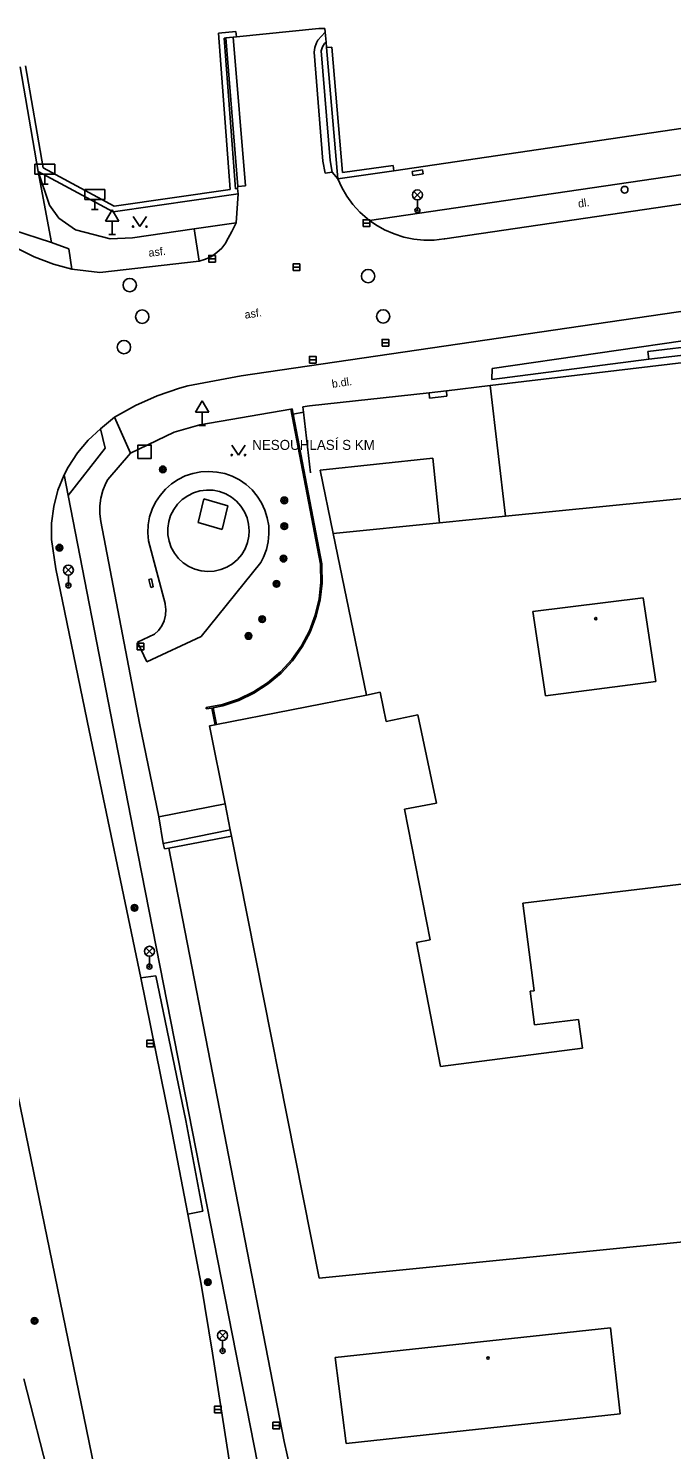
# Model space of a CAD drawing. Extents: x -640201 to -639641, y -1044739 to -1044317.
# Drawn here: x -640117.2 to -640069, y -1044489 to -1044382.5 of the extents above; entities that cross this region are included whole.
import ezdxf

# ---------------------------------------------------------------- set-up
doc = ezdxf.new("R2010")
doc.units = 0
for name, color, linetype in [('Budovy', 7, 'Continuous'), ('Ploty', 7, 'Continuous'), ('Popis objektů', 7, 'Continuous'), ('Popis povrchů', 7, 'Continuous'), ('Pris-HUP', 7, 'Continuous'), ('Rozhraní ploch 1', 7, 'Continuous'), ('Rozhraní ploch 2', 7, 'Continuous'), ('Sloupy_označník', 7, 'Continuous'), ('Vstup na pozemky', 7, 'Continuous'), ('Znaky doprava', 7, 'Continuous'), ('Znaky kanalizace', 7, 'Continuous'), ('Znaky voda', 7, 'Continuous'), ('Značky doprava', 7, 'Continuous'), ('Značky KM', 7, 'Continuous'), ('Značky předmětů', 7, 'Continuous'), ('Šachty ner_', 7, 'Continuous')]:
    doc.layers.add(name, color=color, linetype=linetype)

msp = doc.modelspace()

# ---------------------------------------------------------------- linework, layer by layer
at = {"layer": 'Budovy'}
for p, q in [((-640082.6, -1044409.251), (-640062.223, -1044406.828)), ((-640085.87, -1044409.64), (-640082.6, -1044409.251)), ((-640082.6, -1044409.251), (-640081.44, -1044419.03)), ((-640096.133, -1044410.776), (-640087.17, -1044409.78)), ((-640085.87, -1044409.64), (-640087.17, -1044409.78)), ((-640087.17, -1044409.78), (-640087.127, -1044410.178)), ((-640085.827, -1044410.038), (-640087.127, -1044410.178)), ((-640085.87, -1044409.64), (-640085.827, -1044410.038)), ((-640096.62, -1044410.83), (-640096.133, -1044410.776)), ((-640096.62, -1044410.83), (-640096.574, -1044411.241)), ((-640096.574, -1044411.241), (-640096.068, -1044415.799)), ((-640095.34, -1044415.58), (-640086.88, -1044414.7)), ((-640086.88, -1044414.7), (-640086.4, -1044419.53)), ((-640081.44, -1044419.03), (-640061.28, -1044417.02)), ((-640086.4, -1044419.53), (-640081.44, -1044419.03)), ((-640079.38, -1044426.18), (-640071.11, -1044425.16)), ((-640071.11, -1044425.16), (-640070.18, -1044431.44)), ((-640079.38, -1044426.18), (-640078.44, -1044432.5)), ((-640078.44, -1044432.5), (-640070.18, -1044431.44)), ((-640103.101, -1044434.657), (-640091.86, -1044432.45)), ((-640091.86, -1044432.45), (-640090.84, -1044432.23)), ((-640090.84, -1044432.23), (-640090.38, -1044434.43)), ((-640090.38, -1044434.43), (-640088.01, -1044433.93)), ((-640088.01, -1044433.93), (-640086.62, -1044440.55)), ((-640103.62, -1044434.76), (-640103.199, -1044434.677)), ((-640103.62, -1044434.76), (-640102.459, -1044440.613)), ((-640103.199, -1044434.677), (-640103.101, -1044434.657)), ((-640102.459, -1044440.613), (-640102.073, -1044442.562)), ((-640089, -1044441.01), (-640086.62, -1044440.55)), ((-640089, -1044441.01), (-640087.09, -1044450.79)), ((-640102.073, -1044442.562), (-640101.98, -1044443.03)), ((-640101.98, -1044443.03), (-640095.411, -1044476.154)), ((-640080.14, -1044448.05), (-640061.06, -1044445.76)), ((-640080.14, -1044448.05), (-640079.3, -1044454.62)), ((-640088.12, -1044450.99), (-640087.09, -1044450.79)), ((-640088.12, -1044450.99), (-640086.31, -1044460.29)), ((-640079.6, -1044454.66), (-640079.3, -1044454.62)), ((-640079.6, -1044454.66), (-640079.27, -1044457.18)), ((-640079.27, -1044457.18), (-640075.96, -1044456.76)), ((-640075.96, -1044456.76), (-640075.68, -1044458.93)), ((-640086.31, -1044460.29), (-640075.68, -1044458.93)), ((-640095.411, -1044476.154), (-640065.45, -1044473.17)), ((-640094.2, -1044482.12), (-640073.56, -1044479.89)), ((-640073.56, -1044479.89), (-640072.84, -1044486.33)), ((-640094.2, -1044482.12), (-640093.38, -1044488.55)), ((-640093.38, -1044488.55), (-640072.84, -1044486.33))]:
    msp.add_line(p, q, dxfattribs=at)
at = {"layer": 'Ploty'}
for p, q in [((-640102.958, -1044382.826), (-640101.645, -1044382.712)), ((-640102.958, -1044382.826), (-640102.083, -1044394.544)), ((-640101.61, -1044383.11), (-640101.645, -1044382.712)), ((-640095.44, -1044382.48), (-640094.99, -1044382.47)), ((-640094.99, -1044382.47), (-640094.95, -1044382.76)), ((-640101.686, -1044394.485), (-640102.53, -1044383.19)), ((-640094.85, -1044383.9), (-640094.451, -1044383.866)), ((-640094.85, -1044383.9), (-640094.02, -1044393.74)), ((-640093.657, -1044393.284), (-640094.451, -1044383.866)), ((-640025.49, -1044383.64), (-640089.8, -1044393.14)), ((-640116.46, -1044393.19), (-640117.81, -1044385.35)), ((-640116.099, -1044392.931), (-640117.416, -1044385.282)), ((-640110.86, -1044396.22), (-640116.46, -1044393.19)), ((-640110.786, -1044395.805), (-640116.099, -1044392.931)), ((-640089.8, -1044393.14), (-640094.02, -1044393.74)), ((-640089.856, -1044392.744), (-640093.657, -1044393.284)), ((-640089.8, -1044393.14), (-640089.856, -1044392.744)), ((-640102.083, -1044394.544), (-640110.786, -1044395.805)), ((-640101.686, -1044394.485), (-640101.52, -1044394.46)), ((-640101.47, -1044394.86), (-640101.52, -1044394.46)), ((-640101.47, -1044394.86), (-640110.86, -1044396.22)), ((-640097.52, -1044411.02), (-640097.422, -1044411.001)), ((-640095.31, -1044422.63), (-640097.52, -1044411.02)), ((-640097.348, -1044411.389), (-640097.422, -1044411.001)), ((-640097.348, -1044411.389), (-640096.574, -1044411.241)), ((-640095.211, -1044422.618), (-640097.348, -1044411.389)), ((-640103.877, -1044433.489), (-640103.89, -1044433.39)), ((-640103.199, -1044434.677), (-640103.449, -1044433.424)), ((-640103.101, -1044434.657), (-640103.351, -1044433.406)), ((-640106.67, -1044443.92), (-640101.98, -1044443.03)), ((-640098.02, -1044488.4), (-640106.67, -1044443.92))]:
    msp.add_line(p, q, dxfattribs=at)
for points in [[(-640102.53, -1044383.19), (-640102.406, -1044383.179), (-640101.843, -1044383.13), (-640101.61, -1044383.11)], [(-640096.733, -1044428.751), (-640096.143, -1044427.639), (-640095.7, -1044426.461), (-640095.409, -1044425.237), (-640095.275, -1044423.985), (-640095.301, -1044422.727), (-640095.31, -1044422.63)], [(-640096.671, -1044428.841), (-640096.073, -1044427.727), (-640095.621, -1044426.545), (-640095.321, -1044425.316), (-640095.178, -1044424.059), (-640095.196, -1044422.794), (-640095.211, -1044422.618)], [(-640103.89, -1044433.39), (-640102.655, -1044433.148), (-640101.46, -1044432.75), (-640100.326, -1044432.205), (-640099.27, -1044431.521), (-640098.309, -1044430.708), (-640097.459, -1044429.78), (-640096.733, -1044428.751)], [(-640103.877, -1044433.489), (-640103.449, -1044433.424), (-640103.351, -1044433.406), (-640102.636, -1044433.246), (-640101.435, -1044432.848), (-640100.294, -1044432.302), (-640099.231, -1044431.616), (-640098.262, -1044430.802), (-640097.405, -1044429.872), (-640096.671, -1044428.841)]]:
    msp.add_lwpolyline(points, dxfattribs=at)
at = {"layer": 'Pris-HUP'}
for p, q in [((-640087.656, -1044393.073), (-640088.436, -1044393.193)), ((-640088.436, -1044393.193), (-640088.39, -1044393.49)), ((-640088.39, -1044393.49), (-640087.61, -1044393.37)), ((-640087.656, -1044393.073), (-640087.61, -1044393.37)), ((-640107.98, -1044423.74), (-640108.175, -1044423.786)), ((-640108.035, -1044424.376), (-640108.175, -1044423.786)), ((-640107.84, -1044424.33), (-640108.035, -1044424.376)), ((-640107.84, -1044424.33), (-640107.98, -1044423.74))]:
    msp.add_line(p, q, dxfattribs=at)
at = {"layer": 'Rozhraní ploch 1'}
for p, q in [((-640091.64, -1044396.86), (-640004.24, -1044384.05)), ((-640003.91, -1044386.19), (-640086, -1044398.25)), ((-640094.02, -1044393.74), (-640094.44, -1044393.25)), ((-640101.52, -1044394.46), (-640101.495, -1044394.327)), ((-640101.25, -1044408.51), (-640001.47, -1044393.91)), ((-640082.44, -1044407.96), (-640004.02, -1044396.55)), ((-640113.95, -1044400.53), (-640111.86, -1044400.78)), ((-640111.86, -1044400.78), (-640104.41, -1044399.91)), ((-640070.7, -1044407.27), (-640082.47, -1044408.8)), ((-640082.47, -1044408.8), (-640082.44, -1044407.96)), ((-640105.25, -1044409.26), (-640101.25, -1044408.51)), ((-640111.79, -1044412.49), (-640110.74, -1044411.62)), ((-640104.35, -1044412.18), (-640097.52, -1044411.02)), ((-640111.24, -1044416.3), (-640109.54, -1044414.32)), ((-640101.774, -1044541.352), (-640127.52, -1044416.154)), ((-640114.23, -1044417.48), (-640114.52, -1044415.93)), ((-640110.86, -1044434.83), (-640114.23, -1044417.48)), ((-640108.88, -1044434.55), (-640111.78, -1044419.44)), ((-640115.14, -1044422.98), (-640115.47, -1044420.79)), ((-640108.21, -1044420.89), (-640106.96, -1044425.59)), ((-640112.66, -1044435.11), (-640115.14, -1044422.98)), ((-640104.26, -1044428.06), (-640099.79, -1044422.52)), ((-640107.76, -1044427.89), (-640109.02, -1044428.48)), ((-640109.02, -1044428.48), (-640108.325, -1044429.964)), ((-640104.26, -1044428.06), (-640108.325, -1044429.964)), ((-640108.98, -1044444.45), (-640110.86, -1044434.83)), ((-640107.43, -1044441.57), (-640108.88, -1044434.55)), ((-640108.78, -1044453.65), (-640112.66, -1044435.11)), ((-640102.459, -1044440.613), (-640107.43, -1044441.57)), ((-640107.1, -1044443.58), (-640102.073, -1044442.562)), ((-640107.01, -1044443.98), (-640107.1, -1044443.58)), ((-640096.96, -1044505.67), (-640108.98, -1044444.45)), ((-640106.67, -1044443.92), (-640107.01, -1044443.98)), ((-640107.64, -1044453.49), (-640108.78, -1044453.65)), ((-640106.54, -1044464.61), (-640108.78, -1044453.65)), ((-640105.4, -1044464.34), (-640107.64, -1044453.49)), ((-640105.26, -1044471.36), (-640106.54, -1044464.61)), ((-640104.13, -1044471.13), (-640105.4, -1044464.34)), ((-640105.26, -1044471.36), (-640104.13, -1044471.13)), ((-640104.26, -1044476.62), (-640105.26, -1044471.36)), ((-640103.4, -1044481.78), (-640104.26, -1044476.62)), ((-640099.61, -1044505.95), (-640103.4, -1044481.78)), ((-640117.535, -1044483.704), (-640108.638, -1044518.358))]:
    msp.add_line(p, q, dxfattribs=at)
for points in [[(-640116.46, -1044393.19), (-640115.62, -1044395.73), (-640114.93, -1044396.69), (-640113.67, -1044397.58), (-640111.08, -1044398.25), (-640109.395, -1044398.163)], [(-640094.02, -1044393.74), (-640093.714, -1044394.397), (-640093.327, -1044395.057), (-640092.873, -1044395.673), (-640092.357, -1044396.238), (-640091.785, -1044396.747), (-640091.64, -1044396.86), (-640091.164, -1044397.193), (-640090.499, -1044397.572), (-640089.798, -1044397.879), (-640089.069, -1044398.111), (-640088.319, -1044398.266), (-640087.558, -1044398.343), (-640086.793, -1044398.339), (-640086.032, -1044398.255), (-640086, -1044398.25)], [(-640102.37, -1044398.47), (-640101.95, -1044397.7), (-640101.62, -1044397.05), (-640101.47, -1044394.86)], [(-640109.395, -1044398.163), (-640104.78, -1044397.49), (-640101.62, -1044397.05)], [(-640104.41, -1044399.91), (-640103.932, -1044399.772), (-640103.482, -1044399.56), (-640103.072, -1044399.278), (-640102.712, -1044398.934), (-640102.412, -1044398.537), (-640102.37, -1044398.47)], [(-640118.16, -1044398.9), (-640116.775, -1044399.601), (-640115.325, -1044400.155), (-640113.95, -1044400.53)], [(-640110.74, -1044411.62), (-640109.186, -1044410.747), (-640107.561, -1044410.016), (-640105.876, -1044409.434), (-640105.25, -1044409.26)], [(-640111.79, -1044412.49), (-640112.719, -1044413.338), (-640113.533, -1044414.297), (-640114.219, -1044415.351), (-640114.52, -1044415.93)], [(-640109.54, -1044414.32), (-640106.28, -1044412.73), (-640104.35, -1044412.18)], [(-640108.21, -1044420.89), (-640108.258, -1044420.289), (-640108.227, -1044419.687), (-640108.116, -1044419.095), (-640107.927, -1044418.523), (-640107.665, -1044417.98), (-640107.333, -1044417.477), (-640106.938, -1044417.022), (-640106.485, -1044416.624), (-640105.984, -1044416.289), (-640105.443, -1044416.023), (-640104.872, -1044415.831), (-640104.281, -1044415.717), (-640103.679, -1044415.681), (-640103.078, -1044415.726), (-640102.488, -1044415.849), (-640101.92, -1044416.05)], [(-640114.52, -1044415.93), (-640114.989, -1044417.097), (-640115.307, -1044418.313), (-640115.467, -1044419.56), (-640115.47, -1044420.79)], [(-640111.78, -1044419.44), (-640111.861, -1044418.856), (-640111.861, -1044418.267), (-640111.782, -1044417.683), (-640111.625, -1044417.115), (-640111.393, -1044416.573), (-640111.24, -1044416.3)], [(-640101.92, -1044416.05), (-640101.383, -1044416.324), (-640100.887, -1044416.667), (-640100.441, -1044417.072), (-640100.053, -1044417.533), (-640099.729, -1044418.041), (-640099.474, -1044418.587), (-640099.295, -1044419.163), (-640099.193, -1044419.757), (-640099.171, -1044420.359), (-640099.228, -1044420.959), (-640099.364, -1044421.546), (-640099.577, -1044422.11), (-640099.79, -1044422.52)], [(-640100.653, -1044420.132), (-640100.693, -1044419.64), (-640100.812, -1044419.161), (-640101.006, -1044418.707), (-640101.271, -1044418.29), (-640101.6, -1044417.921), (-640101.984, -1044417.611), (-640102.413, -1044417.366), (-640102.876, -1044417.193), (-640103.36, -1044417.098), (-640103.854, -1044417.081), (-640104.344, -1044417.145), (-640104.817, -1044417.287), (-640105.261, -1044417.503), (-640105.665, -1044417.787), (-640106.017, -1044418.134), (-640106.309, -1044418.532), (-640106.54, -1044418.99), (-640106.683, -1044419.443), (-640106.755, -1044419.931), (-640106.748, -1044420.425)], [(-640106.748, -1044420.425), (-640106.661, -1044420.911), (-640106.496, -1044421.377), (-640106.259, -1044421.811), (-640105.955, -1044422.2), (-640105.593, -1044422.535), (-640105.181, -1044422.808), (-640104.73, -1044423.01), (-640104.253, -1044423.138), (-640103.762, -1044423.186), (-640103.269, -1044423.155), (-640102.787, -1044423.045), (-640102.33, -1044422.858), (-640101.908, -1044422.601), (-640101.534, -1044422.279), (-640101.217, -1044421.9), (-640100.964, -1044421.476), (-640100.783, -1044421.016), (-640100.679, -1044420.533), (-640100.653, -1044420.132)], [(-640107.76, -1044427.89), (-640107.452, -1044427.601), (-640107.204, -1044427.259), (-640107.03, -1044426.89), (-640106.921, -1044426.468), (-640106.896, -1044426.046), (-640106.951, -1044425.628), (-640106.96, -1044425.59)]]:
    msp.add_lwpolyline(points, dxfattribs=at)
at = {"layer": 'Rozhraní ploch 2'}
for p, q in [((-640094.95, -1044382.76), (-640095.5, -1044383.36)), ((-640101.495, -1044394.327), (-640102.406, -1044383.179)), ((-640100.92, -1044394.28), (-640101.843, -1044383.13)), ((-640095.79, -1044384.26), (-640095.14, -1044392.41)), ((-640095.25, -1044384.14), (-640094.58, -1044392.36)), ((-640095.14, -1044392.41), (-640094.97, -1044393.31)), ((-640094.58, -1044392.36), (-640094.44, -1044393.25)), ((-640115.48, -1044398.51), (-640116.46, -1044393.19)), ((-640094.97, -1044393.31), (-640094.44, -1044393.25)), ((-640101.495, -1044394.327), (-640100.92, -1044394.28)), ((-640115.48, -1044398.51), (-640118.39, -1044397.57)), ((-640104.41, -1044399.91), (-640104.78, -1044397.49)), ((-640114.17, -1044398.99), (-640115.48, -1044398.51)), ((-640113.95, -1044400.53), (-640114.17, -1044398.99)), ((-640008.92, -1044399.39), (-640070.77, -1044406.69)), ((-640006.727, -1044399.735), (-640070.7, -1044407.27)), ((-640070.77, -1044406.69), (-640070.7, -1044407.27)), ((-640110.74, -1044411.62), (-640109.54, -1044414.32)), ((-640111.46, -1044413.93), (-640111.79, -1044412.49)), ((-640114.23, -1044417.48), (-640111.46, -1044413.93)), ((-640095.34, -1044415.58), (-640094.36, -1044420.33)), ((-640104.48, -1044419.52), (-640104.05, -1044417.73)), ((-640104.05, -1044417.73), (-640102.25, -1044418.25)), ((-640102.68, -1044420.04), (-640102.25, -1044418.25)), ((-640102.68, -1044420.04), (-640104.48, -1044419.52)), ((-640094.36, -1044420.33), (-640086.4, -1044419.53)), ((-640094.36, -1044420.33), (-640091.86, -1044432.45)), ((-640107.1, -1044443.58), (-640107.43, -1044441.57))]:
    msp.add_line(p, q, dxfattribs=at)
for points in [[(-640095.79, -1044384.26), (-640095.741, -1044383.897), (-640095.614, -1044383.554), (-640095.5, -1044383.36)], [(-640095.25, -1044384.14), (-640095.162, -1044383.859), (-640095, -1044383.61), (-640094.885, -1044383.496)]]:
    msp.add_lwpolyline(points, dxfattribs=at)
at = {"layer": 'Sloupy_označník'}
for centre, radius in [((-640107.12, -1044415.53), 0.25), ((-640107.12, -1044415.53), 0.158), ((-640107.12, -1044415.53), 0.05), ((-640098.02, -1044417.85), 0.25), ((-640098.02, -1044417.85), 0.158), ((-640098.02, -1044417.85), 0.05), ((-640098.02, -1044419.79), 0.25), ((-640098.02, -1044419.79), 0.158), ((-640098.02, -1044419.79), 0.05), ((-640114.88, -1044421.4), 0.25), ((-640114.88, -1044421.4), 0.158), ((-640114.88, -1044421.4), 0.05), ((-640098.08, -1044422.22), 0.25), ((-640098.08, -1044422.22), 0.158), ((-640098.08, -1044422.22), 0.05), ((-640098.6, -1044424.11), 0.25), ((-640098.6, -1044424.11), 0.158), ((-640098.6, -1044424.11), 0.05), ((-640099.68, -1044426.76), 0.25), ((-640099.68, -1044426.76), 0.158), ((-640099.68, -1044426.76), 0.05), ((-640100.7, -1044428.02), 0.25), ((-640100.7, -1044428.02), 0.158), ((-640100.7, -1044428.02), 0.05), ((-640109.25, -1044448.4), 0.25), ((-640109.25, -1044448.4), 0.158), ((-640109.25, -1044448.4), 0.05), ((-640103.75, -1044476.46), 0.25), ((-640103.75, -1044476.46), 0.158), ((-640103.75, -1044476.46), 0.05), ((-640116.737, -1044479.365), 0.25), ((-640116.737, -1044479.365), 0.158), ((-640116.737, -1044479.365), 0.05)]:
    msp.add_circle(centre, radius, dxfattribs=at)
at = {"layer": 'Vstup na pozemky'}
for p, q in [((-640101.61, -1044383.11), (-640095.44, -1044382.48)), ((-640096.84, -1044493.68), (-640098.02, -1044488.4))]:
    msp.add_line(p, q, dxfattribs=at)
msp.add_lwpolyline([(-640094.95, -1044382.76), (-640094.885, -1044383.496), (-640094.85, -1044383.9)], dxfattribs=at)
at = {"layer": 'Znaky doprava'}
for p, q in [((-640088.305, -1044394.685), (-640087.775, -1044395.215)), ((-640088.305, -1044395.215), (-640087.775, -1044394.685)), ((-640088.04, -1044396.1), (-640088.04, -1044395.325)), ((-640114.475, -1044422.815), (-640113.945, -1044423.345)), ((-640114.475, -1044423.345), (-640113.945, -1044422.815)), ((-640114.21, -1044424.23), (-640114.21, -1044423.455)), ((-640108.395, -1044451.395), (-640107.865, -1044451.925)), ((-640108.395, -1044451.925), (-640107.865, -1044451.395)), ((-640108.13, -1044452.81), (-640108.13, -1044452.035)), ((-640102.915, -1044480.195), (-640102.385, -1044480.725)), ((-640102.915, -1044480.725), (-640102.385, -1044480.195)), ((-640102.65, -1044481.61), (-640102.65, -1044480.835))]:
    msp.add_line(p, q, dxfattribs=at)
for centre, radius in [((-640088.04, -1044394.95), 0.375), ((-640088.04, -1044396.1), 0.19), ((-640088.04, -1044396.1), 0.05), ((-640114.21, -1044423.08), 0.375), ((-640114.21, -1044424.23), 0.19), ((-640114.21, -1044424.23), 0.05), ((-640108.13, -1044451.66), 0.375), ((-640108.13, -1044452.81), 0.19), ((-640108.13, -1044452.81), 0.05), ((-640102.65, -1044480.46), 0.375), ((-640102.65, -1044481.61), 0.19), ((-640102.65, -1044481.61), 0.05)]:
    msp.add_circle(centre, radius, dxfattribs=at)
at = {"layer": 'Znaky kanalizace'}
for p, q in [((-640092.12, -1044397.07), (-640091.62, -1044397.07)), ((-640103.18, -1044399.74), (-640103.68, -1044399.74)), ((-640097.36, -1044400.38), (-640096.86, -1044400.38)), ((-640090.69, -1044406.03), (-640090.19, -1044406.03)), ((-640096.14, -1044407.31), (-640095.64, -1044407.31)), ((-640109.06, -1044428.81), (-640108.56, -1044428.81)), ((-640108.33, -1044458.58), (-640107.83, -1044458.58)), ((-640103.25, -1044486), (-640102.75, -1044486)), ((-640098.87, -1044487.22), (-640098.37, -1044487.22))]:
    msp.add_line(p, q, dxfattribs=at)
for points in [[(-640092.12, -1044397.32), (-640091.62, -1044397.32), (-640091.62, -1044396.82), (-640092.12, -1044396.82)], [(-640103.18, -1044399.49), (-640103.68, -1044399.49), (-640103.68, -1044399.99), (-640103.18, -1044399.99)], [(-640097.36, -1044400.63), (-640096.86, -1044400.63), (-640096.86, -1044400.13), (-640097.36, -1044400.13)], [(-640090.69, -1044406.28), (-640090.19, -1044406.28), (-640090.19, -1044405.78), (-640090.69, -1044405.78)], [(-640096.14, -1044407.56), (-640095.64, -1044407.56), (-640095.64, -1044407.06), (-640096.14, -1044407.06)], [(-640109.06, -1044429.06), (-640108.56, -1044429.06), (-640108.56, -1044428.56), (-640109.06, -1044428.56)], [(-640108.33, -1044458.83), (-640107.83, -1044458.83), (-640107.83, -1044458.33), (-640108.33, -1044458.33)], [(-640103.25, -1044486.25), (-640102.75, -1044486.25), (-640102.75, -1044485.75), (-640103.25, -1044485.75)], [(-640098.87, -1044487.47), (-640098.37, -1044487.47), (-640098.37, -1044486.97), (-640098.87, -1044486.97)]]:
    msp.add_lwpolyline(points, close=True, dxfattribs=at)
for centre in [(-640091.74, -1044401.04), (-640109.61, -1044401.71), (-640108.67, -1044404.08), (-640090.61, -1044404.06), (-640110.04, -1044406.36)]:
    msp.add_circle(centre, 0.5, dxfattribs=at)
at = {"layer": 'Znaky voda'}
msp.add_circle((-640072.51, -1044394.56), 0.25, dxfattribs=at)
at = {"layer": 'Značky doprava'}
for p, q in [((-640116.72, -1044392.64), (-640115.22, -1044392.64)), ((-640116.72, -1044393.39), (-640116.72, -1044392.64)), ((-640115.22, -1044393.39), (-640116.72, -1044393.39)), ((-640115.97, -1044393.39), (-640115.97, -1044394.14)), ((-640115.22, -1044392.64), (-640115.22, -1044393.39)), ((-640116.22, -1044394.14), (-640115.72, -1044394.14)), ((-640112.97, -1044394.55), (-640111.47, -1044394.55)), ((-640112.97, -1044395.3), (-640112.97, -1044394.55)), ((-640111.47, -1044394.55), (-640111.47, -1044395.3)), ((-640111.47, -1044395.3), (-640112.97, -1044395.3)), ((-640112.22, -1044395.3), (-640112.22, -1044396.05)), ((-640112.47, -1044396.05), (-640111.97, -1044396.05)), ((-640111.42, -1044396.91), (-640110.92, -1044396.06)), ((-640110.92, -1044396.06), (-640110.42, -1044396.91)), ((-640111.42, -1044396.91), (-640110.42, -1044396.91)), ((-640110.92, -1044397.91), (-640110.92, -1044396.91)), ((-640111.17, -1044397.91), (-640110.67, -1044397.91)), ((-640104.68, -1044411.23), (-640104.18, -1044410.38)), ((-640104.18, -1044410.38), (-640103.68, -1044411.23)), ((-640104.68, -1044411.23), (-640103.68, -1044411.23)), ((-640104.18, -1044412.23), (-640104.18, -1044411.23)), ((-640104.43, -1044412.23), (-640103.93, -1044412.23))]:
    msp.add_line(p, q, dxfattribs=at)
at = {"layer": 'Značky KM'}
for p, q in [((-640109.353, -1044396.577), (-640108.853, -1044397.327)), ((-640108.853, -1044397.327), (-640108.353, -1044396.577)), ((-640101.964, -1044413.702), (-640101.464, -1044414.452)), ((-640101.464, -1044414.452), (-640100.964, -1044413.702))]:
    msp.add_line(p, q, dxfattribs=at)
for centre in [(-640109.353, -1044397.327), (-640108.353, -1044397.327), (-640101.964, -1044414.452), (-640100.964, -1044414.452)]:
    msp.add_circle(centre, 0.05, dxfattribs=at)
at = {"layer": 'Značky předmětů'}
for centre in [(-640074.67, -1044426.72), (-640082.75, -1044482.16)]:
    msp.add_circle(centre, 0.0875, dxfattribs=at)
at = {"layer": 'Šachty ner_'}
msp.add_lwpolyline([(-640108.99, -1044414.71), (-640107.99, -1044414.71), (-640107.99, -1044413.71), (-640108.99, -1044413.71)], close=True, dxfattribs=at)

# ---------------------------------------------------------------- texts
at = {"layer": 'Popis objektů'}
msp.add_text('NESOUHLASÍ S KM', height=0.75, dxfattribs=at).set_placement((-640100.428, -1044414.069))
at = {"layer": 'Popis povrchů'}
for s, rotation, p in [('dl.', 8.28258, (-640075.961, -1044395.914)), ('asf.', 6.66075, (-640108.167, -1044399.594)), ('asf.', 8.32455, (-640100.958, -1044404.235)), ('b.dl.', 8.32455, (-640094.419, -1044409.419))]:
    msp.add_text(s, height=0.6, rotation=rotation, dxfattribs=at).set_placement(p)

doc.saveas('drawing.dxf')
